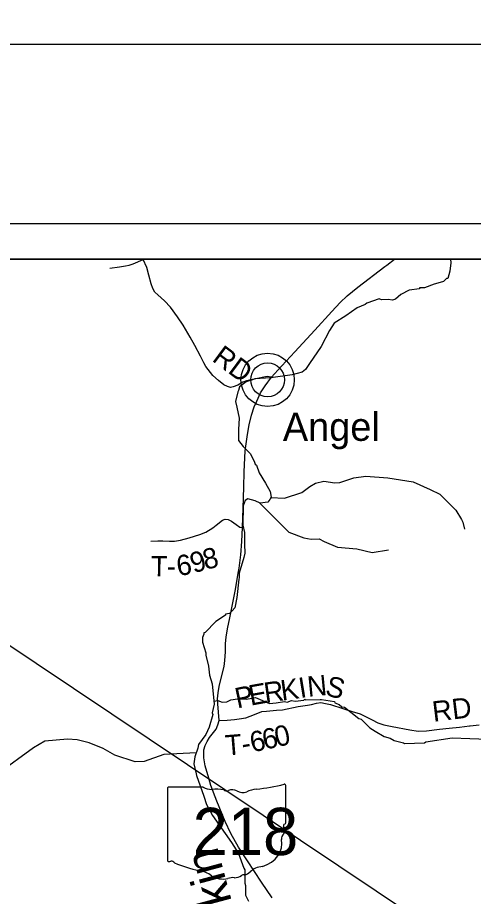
# Model space of a CAD drawing. Extents: x -1.8 to 75.7, y -2 to 25.
# Drawn here: x 4.973 to 6.244, y 19.123 to 21.574 of the extents above; entities that cross this region are included whole.
import ezdxf

# ---------------------------------------------------------------- set-up
doc = ezdxf.new("R2010")
doc.units = 0
for name, color, linetype in [('GM_X_County_Road', 7, 'Continuous'), ('GM_X_County_Road_Text', 7, 'Continuous'), ('GM_X_Minor_River', 7, 'Continuous'), ('GM_X_Minor_River_Text', 7, 'Continuous'), ('GM_X_State_Location', 7, 'Continuous'), ('GM_X_State_Route', 7, 'Continuous'), ('GM_X_State_Shield', 7, 'Continuous'), ('GM_X_Township', 7, 'Continuous'), ('GM_X_Township_Road', 7, 'Continuous'), ('GM_X_Township_Road_Text', 7, 'Continuous'), ('GM_X_Unincorporated', 7, 'Continuous'), ('GM_X_Unincorporated_Location', 7, 'Continuous'), ('GM_X_Unincorporated_Text', 7, 'Continuous'), ('SH_Border', 7, 'Continuous'), ('SH_Data', 7, 'Continuous'), ('TX_P_1', 7, 'Continuous')]:
    doc.layers.add(name, color=color, linetype=linetype)

msp = doc.modelspace()

# ---------------------------------------------------------------- linework, layer by layer
at = {"layer": 'GM_X_County_Road'}
msp.add_lwpolyline([(5.681, 20.5709), (5.6694, 20.5729), (5.6327, 20.5657), (5.6109, 20.5608), (5.6008, 20.5571), (5.5868, 20.5488), (5.5744, 20.5439), (5.5667, 20.5425), (5.5587, 20.5445), (5.548, 20.5494), (5.5331, 20.5617), (5.5176, 20.576), (5.4981, 20.6004), (5.4924, 20.611), (5.4832, 20.6297), (5.4674, 20.6589), (5.4545, 20.6822), (5.4344, 20.7157), (5.4192, 20.7395), (5.3994, 20.7662), (5.3828, 20.7843), (5.3644, 20.8004), (5.3558, 20.8084), (5.3507, 20.8179), (5.3458, 20.8313), (5.3395, 20.8552), (5.3335, 20.877), (5.3231, 20.8988), (5.3226, 20.9)], dxfattribs=at)
at = {"layer": 'GM_X_Minor_River'}
for points in [[(6.1795, 20.9), (6.1806, 20.8899), (6.1784, 20.8667), (6.1727, 20.8466), (6.1685, 20.8462), (6.1599, 20.8382), (6.1383, 20.8309), (6.1345, 20.8301), (6.1077, 20.8198), (6.0933, 20.8202), (6.093, 20.8175), (6.0642, 20.8133), (6.0416, 20.8018), (6.0265, 20.7888), (6.0185, 20.7858), (6.006, 20.7877), (5.9871, 20.7868), (5.9811, 20.7891), (5.9467, 20.7773), (5.9418, 20.7738), (5.9199, 20.7639), (5.8881, 20.7421), (5.8557, 20.7215), (5.8428, 20.701), (5.819, 20.6561), (5.787, 20.6093), (5.7753, 20.5921), (5.7669, 20.5853), (5.7382, 20.5776), (5.6793, 20.5695), (5.6347, 20.5667), (5.6282, 20.564), (5.6108, 20.5579), (5.5923, 20.5442), (5.5886, 20.5335), (5.5871, 20.5305), (5.5807, 20.5035), (5.5845, 20.4872), (5.5909, 20.4571), (5.5894, 20.4248), (5.5891, 20.3948), (5.6023, 20.3773), (5.6224, 20.3569), (5.6337, 20.3341), (5.6353, 20.328), (5.6394, 20.3257), (5.6462, 20.3045), (5.664, 20.2752), (5.6777, 20.2517), (5.68, 20.2361), (5.6773, 20.2319), (5.6762, 20.2297), (5.6709, 20.2228), (5.6493, 20.2193), (5.6354, 20.2265), (5.6153, 20.2314), (5.6074, 20.2268), (5.6025, 20.212), (5.601, 20.1584), (5.6056, 20.1379), (5.6056, 20.1052), (5.6071, 20.0805), (5.6041, 20.0683), (5.5909, 20.0246), (5.5913, 20.0113), (5.5902, 20.0075), (5.5842, 19.9569), (5.5789, 19.928), (5.5714, 19.9189), (5.5638, 19.912), (5.5532, 19.9101), (5.5529, 19.907), (5.526, 19.8899), (5.4958, 19.8586), (5.4924, 19.8582), (5.4924, 19.8541), (5.4887, 19.8453), (5.4883, 19.8316), (5.4982, 19.8024), (5.4978, 19.7952), (5.5058, 19.7652), (5.5084, 19.7401), (5.516, 19.7158), (5.5214, 19.6588), (5.518, 19.6473), (5.5157, 19.6352), (5.5176, 19.6299), (5.5074, 19.5952), (5.498, 19.5743), (5.478, 19.5469)], [(5.6788, 20.235), (5.7177, 20.2338), (5.7654, 20.2493), (5.7883, 20.2664), (5.8037, 20.2754), (5.8265, 20.2808), (5.8573, 20.276), (5.8714, 20.2775), (5.9103, 20.2906), (5.9441, 20.2945), (6.0056, 20.2906), (6.0755, 20.2793), (6.1233, 20.2576), (6.1501, 20.2446), (6.1949, 20.2003), (6.2107, 20.174), (6.2146, 20.1662), (6.2186, 20.1475)], [(5.6482, 20.2199), (5.7297, 20.1389), (5.7707, 20.1228), (5.7918, 20.1191), (5.8137, 20.1199), (5.8279, 20.1123), (5.8645, 20.0967), (5.9191, 20.0923), (5.9611, 20.0818), (6.0075, 20.0894)], [(5.5206, 19.6671), (5.5312, 19.669), (5.5437, 19.6641), (5.5561, 19.6657), (5.5678, 19.671), (5.586, 19.6741), (5.6117, 19.6727), (5.6366, 19.678), (5.6756, 19.6606), (5.6937, 19.6626), (5.7172, 19.6668), (5.7247, 19.6649), (5.7368, 19.6688), (5.7474, 19.6676), (5.7712, 19.6704), (5.7742, 19.673), (5.7761, 19.6708), (5.8162, 19.6716), (5.8207, 19.672), (5.8567, 19.6668), (5.8578, 19.6626), (5.8699, 19.658), (5.8767, 19.652), (5.8843, 19.6509), (5.9247, 19.6194), (5.9312, 19.6175), (5.9546, 19.5932), (5.9698, 19.5838), (5.9947, 19.5686), (6.0121, 19.5637), (6.0231, 19.5573), (6.0492, 19.5509), (6.0515, 19.5494), (6.1074, 19.5514), (6.1112, 19.5541), (6.1845, 19.5649), (6.2333, 19.5631), (6.2843, 19.5613)], [(5.4713, 19.5232), (5.3813, 19.5187), (5.326, 19.4987), (5.301, 19.4978), (5.2447, 19.5165), (5.2119, 19.5357), (5.1727, 19.5514), (5.1393, 19.5592), (5.1127, 19.5614), (5.049, 19.5557), (5.018, 19.537), (4.9171, 19.4643), (4.8937, 19.4421), (4.8714, 19.4268), (4.8286, 19.4247), (4.7636, 19.4297), (4.7069, 19.4036), (4.6963, 19.3986), (4.6944, 19.3982)], [(5.478, 19.5469), (5.4757, 19.5359), (5.4674, 19.5123), (5.4648, 19.4929), (5.4709, 19.4644), (5.472, 19.4602), (5.4929, 19.4025), (5.5001, 19.3789), (5.5167, 19.3486), (5.5694, 19.273), (5.5891, 19.2423), (5.6042, 19.202), (5.6069, 19.1971), (5.6069, 19.1595), (5.6082, 19.153)], [(5.6081, 19.1534), (5.6085, 19.1264), (5.6172, 19.1093)]]:
    msp.add_lwpolyline(points, dxfattribs=at)
at = {"layer": 'GM_X_State_Route'}
for points in [[(5.681, 20.5709), (5.6893, 20.5799), (5.71, 20.6027), (5.7462, 20.6415), (5.802, 20.7025), (5.8496, 20.7542), (5.8723, 20.7788), (5.8915, 20.7979), (5.9214, 20.8223), (5.9971, 20.8796), (6.0023, 20.8836)], [(6.0023, 20.8836), (6.024, 20.9)], [(5.5885, 20.0242), (5.5908, 20.0387), (5.5959, 20.0757), (5.5985, 20.1127), (5.6003, 20.1517), (5.6017, 20.2054), (5.604, 20.2639), (5.6051, 20.3069), (5.608, 20.3655), (5.6106, 20.385), (5.6137, 20.4108), (5.6189, 20.4383), (5.6249, 20.4653), (5.6327, 20.4882), (5.6398, 20.5043), (5.6507, 20.527), (5.6634, 20.5468), (5.681, 20.5709)], [(5.6827, 19.1188), (5.6533, 19.1628), (5.6137, 19.2221), (5.5891, 19.2602), (5.5677, 19.2986), (5.5519, 19.3314), (5.5286, 19.3888), (5.5123, 19.432), (5.506, 19.4522), (5.4965, 19.4874), (5.4927, 19.5093), (5.4929, 19.5312), (5.4963, 19.5433), (5.5014, 19.555), (5.5087, 19.5662), (5.5269, 19.5897), (5.5318, 19.6012), (5.5354, 19.6133), (5.5334, 19.6365), (5.5311, 19.6601), (5.5308, 19.6738), (5.532, 19.6902), (5.5351, 19.708), (5.542, 19.7355), (5.5489, 19.7645), (5.5509, 19.7808), (5.5526, 19.8046), (5.5529, 19.8282), (5.5546, 19.8462), (5.5587, 19.8692), (5.5647, 19.8996), (5.5796, 19.9742), (5.5856, 20.0066), (5.5885, 20.0242)]]:
    msp.add_lwpolyline(points, dxfattribs=at)
at = {"layer": 'GM_X_State_Shield'}
for p, q in [((5.391, 19.4241), (5.391, 19.224)), ((5.4908, 19.4275), (5.3943, 19.4275)), ((5.7206, 19.3278), (5.7206, 19.4325)), ((5.7206, 19.3278), (5.7206, 19.3278))]:
    msp.add_line(p, q, dxfattribs=at)
for centre, major_axis, start_param, end_param in [((5.3948, 19.4245), (0.00382, 0), 1.712693, 3.28349), ((5.5138, 19.4508), (0.037, 0), 4.042523, 4.731795), ((5.526, 19.3152), (0.133, 0), 1.404758, 1.657858), ((5.5562, 19.4256), (0.0107, 0), 3.836095, 5.185415), ((5.5719, 19.4024), (0.0222, 0), 0.950623, 2.079405), ((5.6006, 19.4341), (0.0267, 0), 4.081561, 5.145723), ((5.6478, 19.3664), (0.0703, 0), 1.699011, 2.107814), ((5.6032, 19.7004), (0.3495, 0), 4.814394, 5.042369), ((5.7169, 19.4329), (0.00367, 0), 6.141152, 7.989035), ((5.7197, 19.3201), (0.00568, 0), 1.883978, 3.671073), ((5.6836, 19.3069), (0.0341, 0), 5.934695, 6.695948), ((5.7167, 19.3274), (0.00393, 0), 5.05454, 6.418171), ((5.7337, 19.284), (0.0248, 0), 2.387724, 3.262537), ((5.6228, 19.2707), (0.0874, 0), 5.101752, 6.440018), ((5.3948, 19.2235), (0.00385, 0), 3.00124, 4.508301), ((5.3954, 19.244), (0.0294, 0), 4.665946, 4.897461), ((5.4014, 19.2124), (0.0106, 0), 0.519207, 1.627899), ((5.5352, 19.3922), (0.2524, 0), 4.195997, 4.488961), ((5.46, 19.1341), (0.079, 0), 0.823519, 1.323587), ((5.6596, 19.1678), (0.0479, 0), 1.647645, 2.488434), ((5.5454, 19.2114), (0.0501, 0), 4.026481, 4.996735), ((5.5744, 19.1422), (0.0412, 0), 1.495662, 1.94098), ((5.578, 19.1964), (0.0267, 0), 4.691044, 5.507374), ((5.6022, 19.1771), (0.00752, 0), 1.147584, 2.315152), ((5.599, 19.2046), (0.0282, 0), 4.937069, 5.64225)]:
    msp.add_ellipse(centre, major_axis=major_axis, ratio=0.8, start_param=start_param, end_param=end_param, dxfattribs=at)
at = {"layer": 'GM_X_Township'}
msp.add_lwpolyline([(6.4874, 20.9), (2.1, 20.9), (2.1, 17.3659)], dxfattribs=at)
at = {"layer": 'GM_X_Township_Road'}
for points in [[(5.2302, 20.8752), (5.2577, 20.879), (5.2741, 20.8813), (5.2844, 20.8833), (5.2956, 20.887), (5.3231, 20.8988)], [(5.3449, 20.1139), (5.3647, 20.1145), (5.3779, 20.1147), (5.3971, 20.1133), (5.4103, 20.1139), (5.4273, 20.1162), (5.4519, 20.1225), (5.4666, 20.1271), (5.4815, 20.1325), (5.4976, 20.1383), (5.5171, 20.1509), (5.5265, 20.1581), (5.5443, 20.1721), (5.5515, 20.1747), (5.5601, 20.1738), (5.5696, 20.1695), (5.5828, 20.1601), (5.5928, 20.1529), (5.6003, 20.1517)], [(5.5354, 19.6133), (5.5573, 19.6139), (5.5777, 19.6158), (5.5905, 19.6181), (5.6091, 19.6208), (5.6212, 19.6253), (5.6425, 19.6343), (5.6539, 19.6385), (5.6668, 19.6393), (5.6952, 19.6424), (5.7114, 19.6432), (5.755, 19.6521), (5.7815, 19.656), (5.7921, 19.6583), (5.8063, 19.6616), (5.8181, 19.6633), (5.8318, 19.6613), (5.8452, 19.6577), (5.88, 19.6468), (5.906, 19.6387), (5.9278, 19.6318), (5.9616, 19.6153), (5.9778, 19.6072), (5.9942, 19.6013), (6.0171, 19.5969), (6.0663, 19.5874), (6.0897, 19.5837), (6.1132, 19.5843), (6.1489, 19.5888), (6.1765, 19.5916), (6.205, 19.5952), (6.2328, 19.5986)], [(6.2328, 19.5986), (6.2343, 19.5988), (6.2595, 19.6017)]]:
    msp.add_lwpolyline(points, dxfattribs=at)
at = {"layer": 'GM_X_Unincorporated'}
for radius in [0.0744, 0.0472]:
    msp.add_circle((5.6702, 20.5635), radius, dxfattribs=at)
at = {"layer": 'GM_X_Unincorporated_Location'}
msp.add_line((5.6702, 20.5635), (5.6702, 20.5635), dxfattribs=at)
at = {"layer": 'SH_Border'}
msp.add_lwpolyline([(1.5, 21.5), (33.5, 21.5), (33.5, 0.5), (1.5, 0.5)], close=True, dxfattribs=at)
at = {"layer": 'SH_Data'}
for p, q in [((2, 21), (9, 21)), ((2.1, 20.9), (8.9, 20.9))]:
    msp.add_line(p, q, dxfattribs=at)
at = {"layer": 'TX_P_1'}
msp.add_line((-1.8436, 24.3711), (37.5745, -2.0199), dxfattribs=at)

# ---------------------------------------------------------------- texts
at = {"layer": 'GM_X_County_Road_Text'}
msp.add_text('RD', height=0.05682, rotation=323.3346, dxfattribs=at).set_placement((5.5127, 20.6179))
at = {"layer": 'GM_X_Minor_River_Text'}
msp.add_text('Bullskin', height=0.09471, rotation=105.0011, dxfattribs=at).set_placement((5.6419, 18.8433))
at = {"layer": 'GM_X_State_Location'}
msp.add_text('218', height=0.000189, rotation=0, dxfattribs=at).set_placement((5.4852, 19.2969))
for s in ['s', 'r']:
    msp.add_text(s, height=0.000189, dxfattribs=at).set_placement((5.5521, 19.3107))
at = {"layer": 'GM_X_State_Shield'}
msp.add_text('218', height=0.13184, dxfattribs=at).set_placement((5.4613, 19.2381))
at = {"layer": 'GM_X_Township_Road_Text'}
for s, height, rotation, p in [('6', 0.0568, 8.491, (5.4204, 20.0162)), ('9', 0.0568, 17.1355, (5.4641, 20.0234)), ('8', 0.0568, 13.135, (5.4965, 20.0335)), ('T', 0.0568, 359.1664, (5.3445, 20.0156)), ('-', 0.0568, 1.4176, (5.3894, 20.015)), ('I', 0.0568, 9.3449, (5.7613, 19.6757)), ('N', 0.0568, 5.6243, (5.7833, 19.6794)), ('S', 0.0568, 345.3323, (5.8278, 19.6847)), ('P', 0.0568, 11.7297, (5.5856, 19.6469)), ('E', 0.0568, 10.1916, (5.6227, 19.6546)), ('R', 0.0568, 8.1475, (5.664, 19.662)), ('K', 0.0568, 7.8733, (5.7102, 19.6686)), ('RD', 0.05682, 6.8826, (6.1324, 19.6097)), ('6', 0.0568, 11.9572, (5.6272, 19.5242)), ('6', 0.0568, 12.3763, (5.6618, 19.5315)), ('0', 0.0568, 12.4732, (5.6961, 19.539)), ('T', 0.0568, 4.5907, (5.5539, 19.5156)), ('-', 0.0568, 9.9309, (5.602, 19.5197))]:
    msp.add_text(s, height=height, rotation=rotation, dxfattribs=at).set_placement(p)
at = {"layer": 'GM_X_Unincorporated_Text'}
msp.add_text('Angel', height=0.07898, rotation=0, dxfattribs=at).set_placement((5.7127, 20.3933))

doc.saveas('drawing.dxf')
